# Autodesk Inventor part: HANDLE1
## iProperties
Author: GJOHNST2
Shininess: 20.0
Length Units: 11272
Angle Units: 11286
Time Units: 11279
Mass Units: 11290
Length Display Precision: 3
Angle Display Precision: 2
Compacted: True
PropertySet Name: _Private Model Information
Created: 2001-11
Part Number: HANDLE1
Material: Stainless Steel, Austenitic
Document SubType Name: Modeling
Designer: GJOHNST2
Control State: 0
Master: False
Checked Out: False
PropertySet Name: Design Tracking Control
Density: 8.03
Volumn: 33.562316364783484
Area: 142.61751534460228
PropertySet Name: Model Information
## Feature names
1. Derived Body1 [Tagging]
